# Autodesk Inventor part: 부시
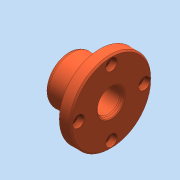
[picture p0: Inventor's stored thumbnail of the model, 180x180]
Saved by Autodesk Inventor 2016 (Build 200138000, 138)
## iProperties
Created: 2024-09
Part Number: 부시
Material: 일반
Document SubType Name: Modeling
Designer: pc-7
Density: 1 g/cm^3
Appearance: 기본값
Author: jhkim
Sending System: Autodesk Inventor 2025
Preprocessor: ST-DEVELOPER v20
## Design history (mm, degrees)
node "부시1"
node "솔리드2"
node "솔리드1"
